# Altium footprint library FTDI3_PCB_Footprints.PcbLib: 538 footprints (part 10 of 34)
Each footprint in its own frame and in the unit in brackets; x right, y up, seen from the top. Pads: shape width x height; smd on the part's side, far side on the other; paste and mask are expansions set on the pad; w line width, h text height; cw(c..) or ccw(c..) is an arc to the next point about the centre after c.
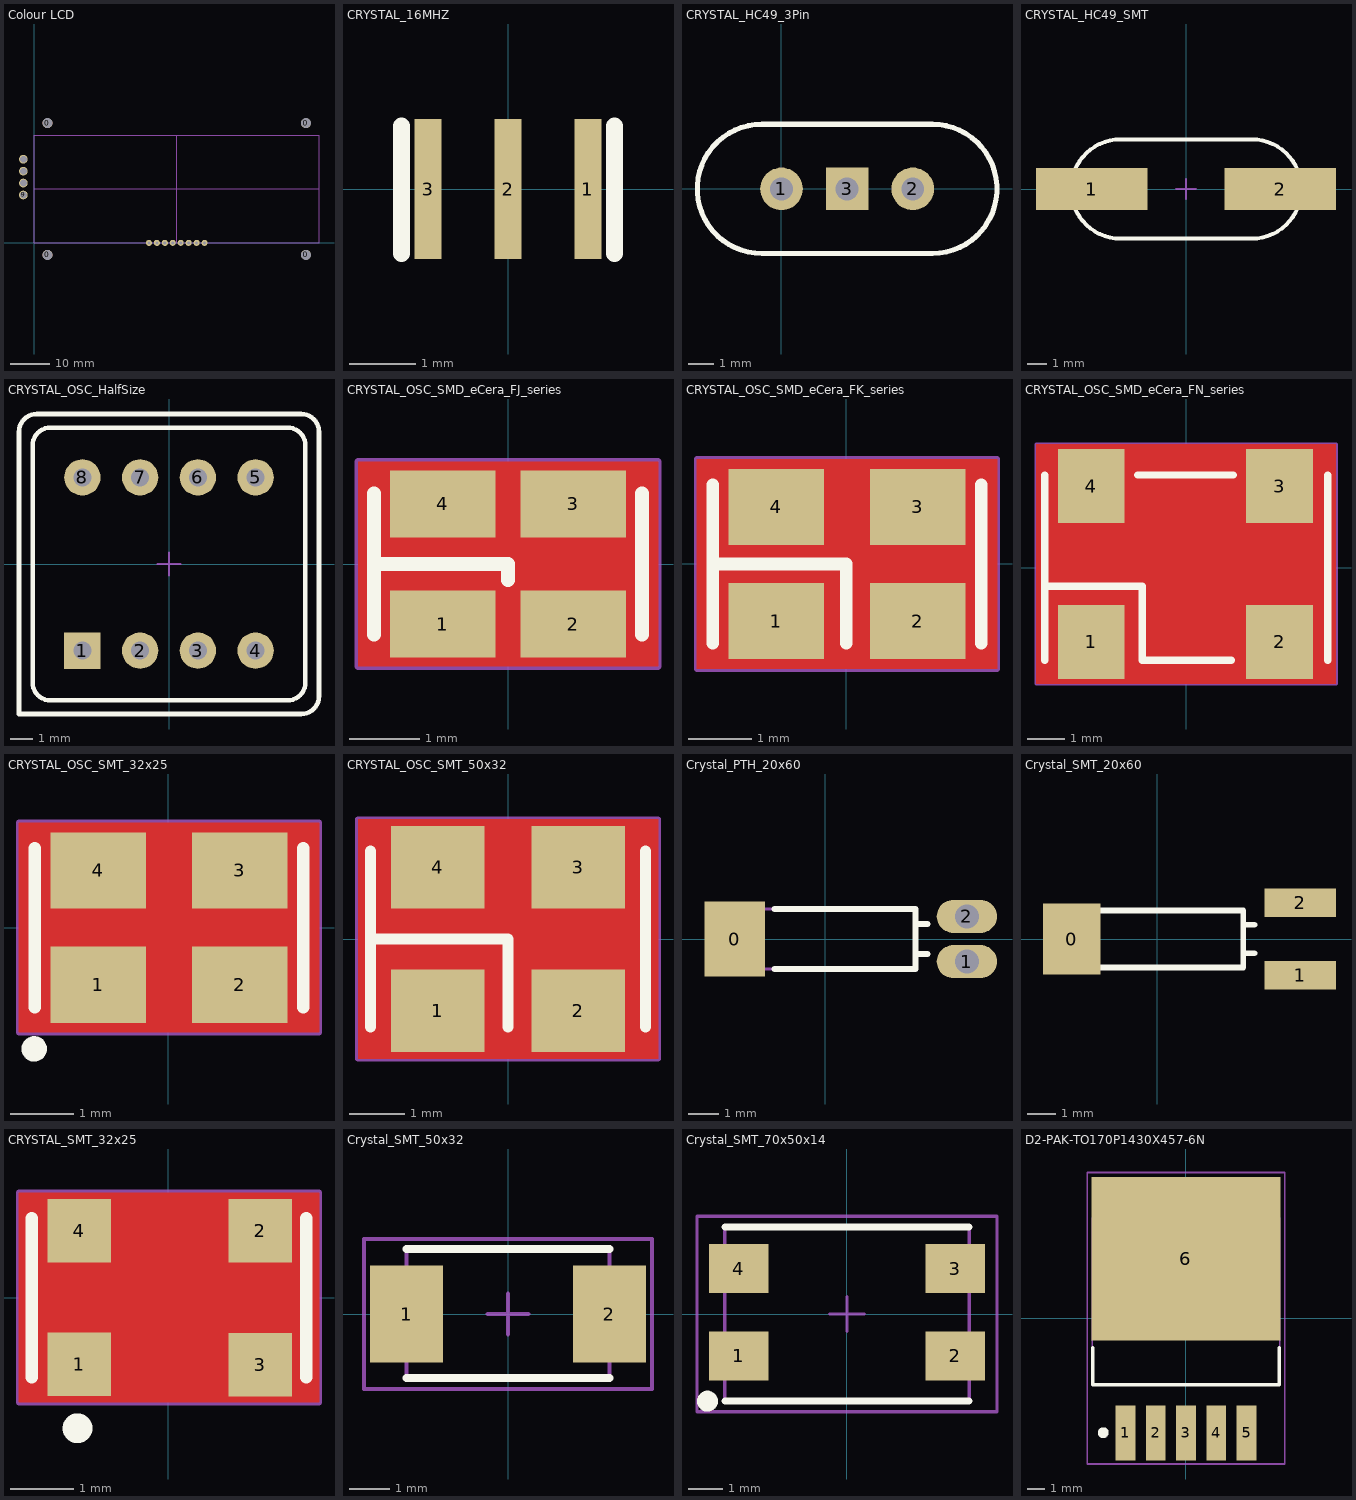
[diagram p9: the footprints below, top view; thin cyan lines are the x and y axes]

## Colour LCD [mm]
pads (16):
  round 2.5 hole 2.5 unplated: 0(3.3,30.1) 0(3.3,-3) 0(68.3,30.1) 0(68.3,-3)
  round 1.524 hole 0.8: 1(42.814,0) 2(40.814,0) 3(38.814,0) 4(36.814,0) 5(34.814,0) 6(32.814,0) 7(30.814,0) 8(28.814,0)
  round 2.2 hole 1.7: 9(-2.769,12.042) 10(-2.769,21.042) 11(-2.769,18.042) 12(-2.769,15.042)
M13_Assembly_Info:
  lines w0.254: 0,13.55 71.6,13.55 ; 35.8,0 35.8,27.1 ; 0,0 0,27.1 71.6,27.1 71.6,0 0,0

## CRYSTAL_16MHZ [mm] "CRYSTAL SMT 16MHZ"
height 1
pads (3):
  rect 0.4x2.1 smd: 1(1.2,0) 2(0,0) 3(-1.2,0)
Top Overlay:
  lines w0.254: -1.6,-0.965 -1.6,0.943 ; 1.6,-0.965 1.6,0.943

## CRYSTAL_HC49_3Pin [mil] "Crystal with ground pin"
pads (3):
  round 65 hole 35: 1(0,0) 2(200,0)
  rect 65x65 hole 35: 3(100,0)
Top Overlay:
  lines w7.87: -29.92,-98.43 cw(c-29.92,0) -29.92,98.43 229.92,98.43 cw(c229.92,0) 229.92,-98.43 -29.92,-98.43
M13_Assembly_Info:
  lines w3.94: -30.31,-98.82 cw(c-30.31,-0.39) -30.31,98.03 229.53,98.03 cw(c229.53,-0.39) 229.53,-98.82 -30.31,-98.82
3D body: height 138.4, standoff -156.88, extent -123.43,-91.34 323.43,91.73

## CRYSTAL_HC49_SMT [mm] "Crystal SMT"
pads (2):
  rect 5.6x2.1 smd: 1(-4.75,0) 2(4.75,0)
Top Overlay:
  lines w0.2: -3.29,-2.5 cw(c-3.29,0) -3.29,2.5 3.31,2.5 cw(c3.31,0) 3.31,-2.5 -3.29,-2.5
M13_Assembly_Info:
  lines w0.1: -3.3,-2.51 cw(c-3.3,-0.01) -3.3,2.49 3.3,2.49 cw(c3.3,-0.01) 3.3,-2.51 -3.3,-2.51
M15_Country_Yard:
  lines w0.1: -0.5,0 0.5,0 ; 0,-0.5 0,0.5
3D body: height 3.52, standoff -3.98, extent -5.665,-2.32 5.685,2.33

## CRYSTAL_OSC_HalfSize [mm] "DIP; 8 Leads; Row Spacing 7.62 mm; Pitch 2.54 mm"
height 5.33
pads (8):
  rect 1.6x1.6 hole 0.8: 1(-3.81,-3.81)
  round 1.6 hole 0.8: 2(-1.27,-3.81) 3(1.27,-3.81) 4(3.81,-3.81) 5(3.81,3.81) 6(1.27,3.81) 7(-1.27,3.81) 8(-3.81,3.81)
Top Overlay:
  lines w0.2: -6.6,-6.6 5.82,-6.6 ccw(c5.82,-5.82) 6.6,-5.82 6.6,5.82 ccw(c5.82,5.82) 5.82,6.6 -5.82,6.6 ccw(c-5.82,5.82) -6.6,5.82 -6.6,-6.6 ; -6,-5.22 ccw(c-5.22,-5.22) -5.22,-6 5.22,-6 ccw(c5.22,-5.22) 6,-5.22 6,5.22 ccw(c5.22,5.22) 5.22,6 -5.22,6 ccw(c-5.22,5.22) -6,5.22 -6,-5.22
M13_Assembly_Info:
  lines w0.1: -6.6,-6.6 5.82,-6.6 ccw(c5.82,-5.82) 6.6,-5.82 6.6,5.82 ccw(c5.82,5.82) 5.82,6.6 -5.82,6.6 ccw(c-5.82,5.82) -6.6,5.82 -6.6,-6.6
M15_Country_Yard:
  lines w0.1: -0.5,0 0.5,0 ; 0,-0.5 0,0.5
3D body: height 0, standoff 0, extent -6.6,-6.6 6.6,6.6

## CRYSTAL_OSC_SMD_eCera_FJ_series [mm] "eCera; FJ series; 3.3V CMOS; Low Jitter; Seam Sealed Crystal Clock Oscillator; 2.5x2mm"
height 0.9
pads (4):
  rect 1.5x0.95 smd: 1(-0.925,-0.85) 2(0.925,-0.85) 3(0.925,0.85) 4(-0.925,0.85)
Top Layer:
  pour cut-out: -2.125,1.45 2.125,1.45 2.125,-1.45 -2.125,-1.45
Top Overlay:
  lines w0.2: -1.9,-1 -1.9,1 ; -1.9,0 0,0 0,-0.225 ; 1.9,-1 1.9,1
M13_Assembly_Info:
  circle w0.2: c-0.95,-0.675 r0.1
  lines w0.1: -1.25,-1 -1.25,1 1.25,1 1.25,-1 -1.25,-1
M15_Country_Yard:
  lines w0.1: -0.5,0 0.5,0 ; 0,-0.5 0,0.5 ; -2.125,-1.45 2.125,-1.45 2.125,1.45 -2.125,1.45 -2.125,-1.45
3D body: height 0, standoff 0, extent -1.25,-1 1.25,1

## CRYSTAL_OSC_SMD_eCera_FK_series [mm] "eCera; FK series; 3.3V CMOS; Low Jitter; Seam Sealed Crystal Clock Oscillator; 3.2x2.5mm"
height 1
pads (4):
  rect 1.5x1.2 smd: 1(-1.1,-0.9) 2(1.125,-0.9) 3(1.125,0.9) 4(-1.1,0.9)
Top Layer:
  pour cut-out: -2.35,1.65 2.375,1.65 2.375,-1.65 -2.35,-1.65
Top Overlay:
  lines w0.2: -2.1,-1.25 -2.1,1.25 ; -2.1,0 0,0 0,-1.25 ; 2.125,-1.25 2.125,1.25
M13_Assembly_Info:
  circle w0.2: c-1.275,-0.925 r0.1
  lines w0.1: -1.6,-1.25 -1.6,1.25 1.6,1.25 1.6,-1.25 -1.6,-1.25
M15_Country_Yard:
  lines w0.1: -0.5,0 0.5,0 ; 0,-0.5 0,0.5 ; -2.35,-1.65 -2.35,1.65 2.375,1.65 2.375,-1.65 -2.35,-1.65
3D body: height 0, standoff 0, extent -1.6,-1.25 1.6,1.25

## CRYSTAL_OSC_SMD_eCera_FN_series [mm] "eCera; FN series; 3.3V CMOS; Low Jitter; Seam Sealed Crystal Clock Oscillator; 7x5mm"
height 1.4
pads (4):
  rect 1.8x2 smd: 1(-2.562,-2) 2(2.518,-2) 3(2.518,2.2) 4(-2.562,2.2)
Top Layer:
  pour cut-out: -4.05,3.325 4.025,3.325 4.025,-3.125 -4.05,-3.125
Top Overlay:
  lines w0.2: -3.812,-2.5 -3.812,2.5 ; -3.812,-0.5 -1.187,-0.5 -1.187,-2.5 1.213,-2.5 ; -1.312,2.5 1.263,2.5 ; 3.813,-2.5 3.813,2.5
M13_Assembly_Info:
  circle w0.2: c-3.487,-2.15 r0.1
  lines w0.1: -3.812,-2.5 -3.812,2.5 3.813,2.5 3.813,-2.5 -3.812,-2.5
M15_Country_Yard:
  lines w0.1: -0.5,0 0.5,0 ; 0,-0.5 0,0.5 ; -4.038,-3.125 4.038,-3.125 4.038,3.325 -4.038,3.325 -4.038,-3.125
3D body: height 0, standoff 0, extent -3.812,-2.5 3.813,2.5

## CRYSTAL_OSC_SMT_32x25 [mm] "3.3V CMOS; Low Jitter; Crystal Clock Oscillator; 3.2x2.5mm"
height 1
pads (4):
  rect 1.5x1.2 smd: 1(-1.1,-0.9) 2(1.125,-0.9) 3(1.125,0.9) 4(-1.1,0.9)
Top Layer:
  pour cut-out: -2.35,1.65 2.375,1.65 2.375,-1.65 -2.35,-1.65
Top Overlay:
  circle w0.2: c-2.11,-1.91 r0.1
  lines w0.2: -2.1,-1.25 -2.1,1.25 ; 2.125,-1.25 2.125,1.25
M13_Assembly_Info:
  circle w0.2: c-1.275,-0.925 r0.1
  lines w0.1: -1.6,-1.25 1.6,-1.25 1.6,1.25 -1.6,1.25 -1.6,-1.25
M15_Country_Yard:
  lines w0.1: -0.5,0 0.5,0 ; 0,-0.5 0,0.5 ; -2.35,-1.65 2.375,-1.65 2.375,1.65 -2.35,1.65 -2.35,-1.65
3D body: height 0, standoff 0, extent -1.6,-1.25 1.6,1.25

## CRYSTAL_OSC_SMT_50x32 [mm] "3.3V CMOS; Low Jitter; Crystal Clock Oscillator; 5.0x3.2mm"
height 1.2
pads (4):
  rect 1.7x1.5 smd: 1(-1.275,-1.3) 2(1.275,-1.3) 3(1.275,1.3) 4(-1.275,1.3)
Top Layer:
  pour cut-out: -2.725,2.175 2.725,2.175 2.725,-2.175 -2.725,-2.175
Top Overlay:
  lines w0.2: -2.5,-1.6 -2.5,1.6 ; -2.5,0 0,0 0,-1.6 ; 2.5,-1.6 2.5,1.6
M13_Assembly_Info:
  circle w0.2: c-2.15,-1.225 r0.1
  lines w0.1: -2.5,-1.6 2.5,-1.6 2.5,1.6 -2.5,1.6 -2.5,-1.6
M15_Country_Yard:
  lines w0.1: -0.5,0 0.5,0 ; 0,-0.5 0,0.5 ; -2.725,-2.175 -2.725,2.175 2.725,2.175 2.725,-2.175 -2.725,-2.175
3D body: height 0, standoff 0, extent -2.5,-1.6 2.5,1.6

## Crystal_PTH_20x60 [mm] "Tuning Fork Quartz Crystal; 32.768kHz; PTH"
height 2
pads (3):
  rect 2x2.5 smd: 0(-3,0)
  oval 2x1.1 hole 0.8: 1(4.7,-0.75) 2(4.7,0.75)
Top Overlay:
  lines w0.2: -1.68,-1 3,-1 3,1 -1.68,1 ; 3,-0.5 3.4,-0.5 ; 3,0.5 3.4,0.5
M13_Assembly_Info:
  lines w0.1: -3,-1 -3,1 3,1 3,-1 -3,-1
3D body: height 2, standoff 0, extent -3,-1 3,1

## Crystal_SMT_20x60 [mm] "Tuning Fork Quartz Crystal; 32.768kHz; SMD"
height 2
pads (3):
  rect 2x2.5 smd: 0(-3,0)
  rect 2.5x1 smd: 1(5,-1.275) 2(5,1.275)
Top Overlay:
  lines w0.2: 3,-0.5 3.4,-0.5 ; 3,0.5 3.4,0.5 ; -3,-1 3,-1 3,1 -3,1 -3,-1
M13_Assembly_Info:
  lines w0.1: -3,-1 3,-1 3,1 -3,1 -3,-1
3D body: height 2, standoff 0, extent -3,-1 3,1

## CRYSTAL_SMT_32x25 [mm] "Seam Sealed Crystal; 3.2x2.5mm"
height 1
pads (4):
  rect 1x1 smd: 1(-1.4,-1.05) 2(1.45,1.05) 3(1.45,-1.06) 4(-1.4,1.05)
Top Layer:
  pour cut-out: -2.35,1.65 2.375,1.65 2.375,-1.65 -2.35,-1.65
Top Overlay:
  circle w0.254: c-1.429,-2.057 r0.108
  lines w0.2: -2.15,-1.25 -2.15,1.25 ; 2.175,-1.25 2.175,1.25
M13_Assembly_Info:
  circle w0.2: c-1.275,-0.925 r0.1
  lines w0.1: -1.6,-1.25 1.6,-1.25 1.6,1.25 -1.6,1.25 -1.6,-1.25
M15_Country_Yard:
  lines w0.1: -0.5,0 0.5,0 ; 0,-0.5 0,0.5 ; -2.35,-1.65 2.375,-1.65 2.375,1.65 -2.35,1.65 -2.35,-1.65
3D body: height 0, standoff 0, extent -1.6,-1.25 1.6,1.25

## Crystal_SMT_50x32 [mm] "Quartz Crystal; 5.0x3.2mm"
height 1.3
pads (2):
  rect 1.8x2.4 smd: 1(-2.5,0) 2(2.5,0)
Top Overlay:
  lines w0.2: -2.5,-1.575 2.5,-1.575 ; -2.5,1.6 2.5,1.6
M13_Assembly_Info:
  lines w0.1: -2.5,-1.6 2.5,-1.6 2.5,1.6 -2.5,1.6 -2.5,-1.6
M15_Country_Yard:
  lines w0.1: -0.5,0 0.5,0 ; 0,-0.5 0,0.5 ; -3.55,-1.85 -3.55,1.85 3.55,1.85 3.55,-1.85 -3.55,-1.85
3D body: height 0, standoff 0, extent -2.5,-1.6 2.5,1.6

## Crystal_SMT_70x50x14 [mm] "Quartz Crystal; 7.0x5.0mm"
height 1.25
pads (4):
  rect 1.7x1.4 smd: 1(-3.1,-1.2) 2(3.1,-1.2) 3(3.1,1.3) 4(-3.1,1.3)
Top Overlay:
  circle w0.4: c-4,-2.5 r0.1
  lines w0.2: -3.5,-2.5 3.5,-2.5 ; -3.5,2.5 3.5,2.5
M13_Assembly_Info:
  lines w0.1: -3.5,-2.5 -3.5,2.5 3.5,2.5 3.5,-2.5 -3.5,-2.5
M15_Country_Yard:
  lines w0.1: -0.5,0 0.5,0 ; 0,-0.5 0,0.5 ; -4.3,-2.8 4.3,-2.8 4.3,2.8 -4.3,2.8 -4.3,-2.8
3D body: height 0, standoff 0, extent -3.5,-2.5 3.5,2.5

## D2-PAK-TO170P1430X457-6N [mm] "D2-PAK, 6-Pads, Body 9.4x10.5mm (max), IPC Medium Density"
height 4.572
pads (6):
  rect 1.1x3.1 smd: 1(-3.404,-6.45) 2(-1.702,-6.45) 3(0,-6.45) 4(1.702,-6.45) 5(3.404,-6.45)
  rect 10.65x9.2 smd: 6(0,3.35)
Top Overlay:
  circle w0.3: c-4.656,-6.44 r0.156
  lines w0.2: -5.25,-1.65 -5.25,-3.75 5.25,-3.75 5.25,-1.65
M13_Assembly_Info:
  lines w0.1: -5.275,-3.75 -5.275,5.65 5.275,5.65 5.275,-3.75 -5.275,-3.75
M15_Country_Yard:
  lines w0.1: -0.5,0 0.5,0 ; 0,-0.5 0,0.5 ; -5.55,-8.2 -5.55,8.2 5.55,8.2 5.55,-8.2 -5.55,-8.2
3D body: height 4.57, standoff 0.1, extent -5.275,-3.75 5.275,5.65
